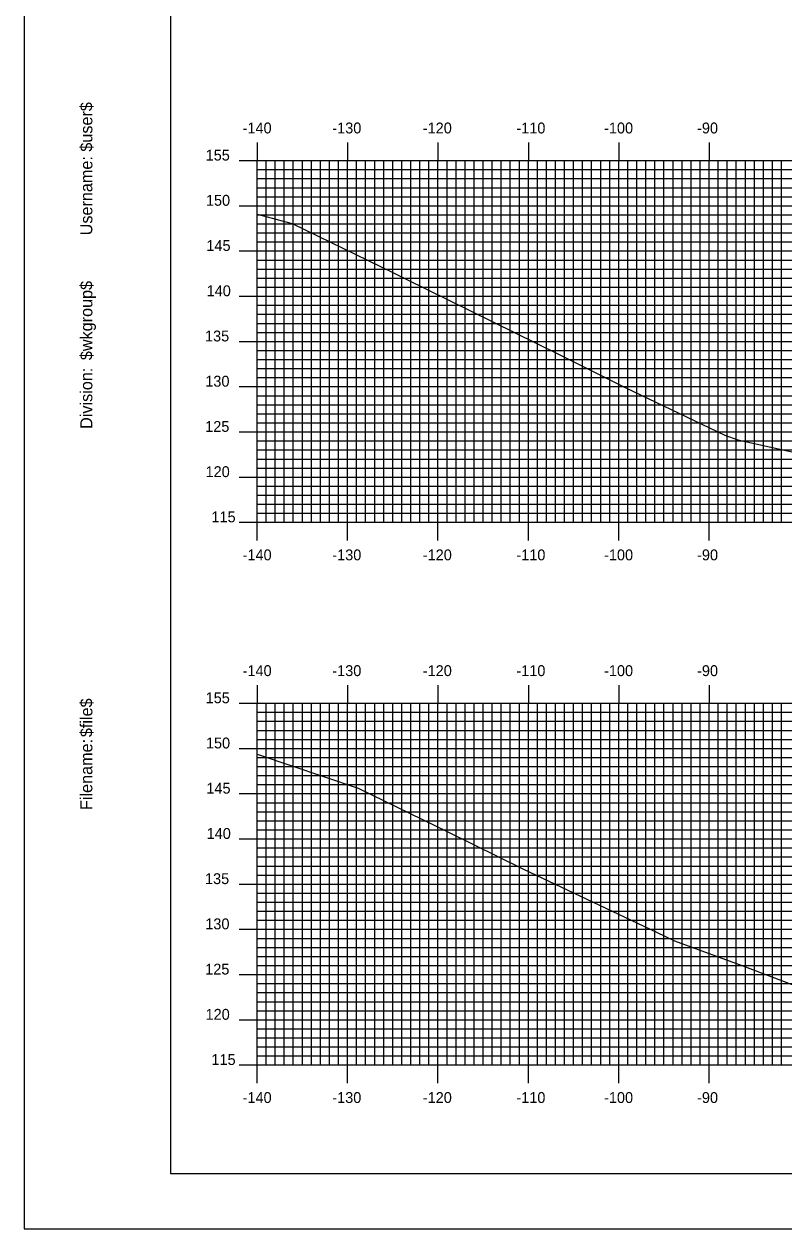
# Model space of a CAD drawing. Extents: x 851926 to 852269, y 366605 to 366825.
# Drawn here: x 851926.2 to 852010.2, y 366604.9 to 366738.1 of the extents above; entities that cross this region are included whole.
import ezdxf

# ---------------------------------------------------------------- set-up
doc = ezdxf.new("R2010")
doc.units = 0
for name, color, linetype in [('BORDER', 7, 'Continuous'), ('H_V ANNOTATION', 7, 'Continuous'), ('MAJOR', 7, 'Continuous'), ('MINOR', 7, 'Continuous'), ('PLOT BOUNDARY', 7, 'Continuous'), ('S_Roadway_Centerline', 7, 'Continuous')]:
    doc.layers.add(name, color=color, linetype=linetype)

msp = doc.modelspace()

# ---------------------------------------------------------------- linework, layer by layer
at = {"layer": 'BORDER'}
msp.add_lwpolyline([(851942.36, 366611.06), (852262.36, 366611.06), (852262.36, 366821.06), (851942.36, 366821.06)], close=True, dxfattribs=at)
at = {"layer": 'MAJOR'}
for p, q in [((851951.96, 366725.06), (851951.96, 366723.06)), ((851961.96, 366725.06), (851961.96, 366723.06)), ((851971.96, 366725.06), (851971.96, 366723.06)), ((851981.96, 366725.06), (851981.96, 366723.06)), ((851991.96, 366725.06), (851991.96, 366723.06)), ((852001.96, 366725.06), (852001.96, 366723.06)), ((851949.96, 366723.06), (851951.96, 366723.06)), ((851951.96, 366723.06), (852231.96, 366723.06)), ((851951.96, 366683.06), (851951.96, 366723.06)), ((851951.96, 366683.06), (851951.96, 366723.06)), ((851951.96, 366723.06), (852231.96, 366723.06)), ((851961.96, 366683.06), (851961.96, 366723.06)), ((851971.96, 366683.06), (851971.96, 366723.06)), ((851981.96, 366683.06), (851981.96, 366723.06)), ((851991.96, 366683.06), (851991.96, 366723.06)), ((852001.96, 366683.06), (852001.96, 366723.06)), ((851949.96, 366718.06), (851951.96, 366718.06)), ((851951.96, 366718.06), (852231.96, 366718.06)), ((851949.96, 366713.06), (851951.96, 366713.06)), ((851951.96, 366713.06), (852231.96, 366713.06)), ((851949.96, 366708.06), (851951.96, 366708.06)), ((851951.96, 366708.06), (852231.96, 366708.06)), ((851949.96, 366703.06), (851951.96, 366703.06)), ((851951.96, 366703.06), (852231.96, 366703.06)), ((851949.96, 366698.06), (851951.96, 366698.06)), ((851951.96, 366698.06), (852231.96, 366698.06)), ((851949.96, 366693.06), (851951.96, 366693.06)), ((851951.96, 366693.06), (852231.96, 366693.06)), ((851949.96, 366688.06), (851951.96, 366688.06)), ((851951.96, 366688.06), (852231.96, 366688.06)), ((851949.96, 366683.06), (851951.96, 366683.06)), ((851951.96, 366683.06), (852231.96, 366683.06)), ((851951.96, 366683.06), (852231.96, 366683.06)), ((851951.96, 366681.05), (851951.96, 366683.06)), ((851961.96, 366681.05), (851961.96, 366683.06)), ((851971.96, 366681.05), (851971.96, 366683.06)), ((851981.96, 366681.05), (851981.96, 366683.06)), ((851991.96, 366681.05), (851991.96, 366683.06)), ((852001.96, 366681.05), (852001.96, 366683.06)), ((851951.96, 366665.06), (851951.96, 366663.06)), ((851961.96, 366665.06), (851961.96, 366663.06)), ((851971.96, 366665.06), (851971.96, 366663.06)), ((851981.96, 366665.06), (851981.96, 366663.06)), ((851991.96, 366665.06), (851991.96, 366663.06)), ((852001.96, 366665.06), (852001.96, 366663.06)), ((851949.96, 366663.06), (851951.96, 366663.06)), ((851951.96, 366663.06), (852231.96, 366663.06)), ((851951.96, 366623.06), (851951.96, 366663.06)), ((851951.96, 366623.06), (851951.96, 366663.06)), ((851951.96, 366663.06), (852231.96, 366663.06)), ((851961.96, 366623.06), (851961.96, 366663.06)), ((851971.96, 366623.06), (851971.96, 366663.06)), ((851981.96, 366623.06), (851981.96, 366663.06)), ((851991.96, 366623.06), (851991.96, 366663.06)), ((852001.96, 366623.06), (852001.96, 366663.06)), ((851949.96, 366658.06), (851951.96, 366658.06)), ((851951.96, 366658.06), (852231.96, 366658.06)), ((851949.96, 366653.06), (851951.96, 366653.06)), ((851951.96, 366653.06), (852231.96, 366653.06)), ((851949.96, 366648.06), (851951.96, 366648.06)), ((851951.96, 366648.06), (852231.96, 366648.06)), ((851949.96, 366643.06), (851951.96, 366643.06)), ((851951.96, 366643.06), (852231.96, 366643.06)), ((851949.96, 366638.06), (851951.96, 366638.06)), ((851951.96, 366638.06), (852231.96, 366638.06)), ((851949.96, 366633.06), (851951.96, 366633.06)), ((851951.96, 366633.06), (852231.96, 366633.06)), ((851949.96, 366628.06), (851951.96, 366628.06)), ((851951.96, 366628.06), (852231.96, 366628.06)), ((851949.96, 366623.06), (851951.96, 366623.06)), ((851951.96, 366623.06), (852231.96, 366623.06)), ((851951.96, 366623.06), (852231.96, 366623.06)), ((851951.96, 366621.05), (851951.96, 366623.06)), ((851961.96, 366621.05), (851961.96, 366623.06)), ((851971.96, 366621.05), (851971.96, 366623.06)), ((851981.96, 366621.05), (851981.96, 366623.06)), ((851991.96, 366621.05), (851991.96, 366623.06)), ((852001.96, 366621.05), (852001.96, 366623.06))]:
    msp.add_line(p, q, dxfattribs=at)
at = {"layer": 'MINOR'}
for p, q in [((851951.96, 366722.06), (852231.96, 366722.06)), ((851951.96, 366722.06), (851953.97, 366722.06)), ((851952.96, 366683.06), (851952.96, 366723.06)), ((851953.96, 366683.06), (851953.96, 366723.06)), ((851954.96, 366683.06), (851954.96, 366723.06)), ((851955.96, 366683.06), (851955.96, 366723.06)), ((851956.96, 366683.06), (851956.96, 366723.06)), ((851957.96, 366683.06), (851957.96, 366723.06)), ((851958.96, 366683.06), (851958.96, 366723.06)), ((851959.96, 366683.06), (851959.96, 366723.06)), ((851960.96, 366683.06), (851960.96, 366723.06)), ((851962.96, 366683.06), (851962.96, 366723.06)), ((851963.96, 366683.06), (851963.96, 366723.06)), ((851964.96, 366683.06), (851964.96, 366723.06)), ((851965.96, 366683.06), (851965.96, 366723.06)), ((851966.96, 366683.06), (851966.96, 366723.06)), ((851967.96, 366683.06), (851967.96, 366723.06)), ((851968.96, 366683.06), (851968.96, 366723.06)), ((851969.96, 366683.06), (851969.96, 366723.06)), ((851970.96, 366683.06), (851970.96, 366723.06)), ((851972.96, 366683.06), (851972.96, 366723.06)), ((851973.96, 366683.06), (851973.96, 366723.06)), ((851974.96, 366683.06), (851974.96, 366723.06)), ((851975.96, 366683.06), (851975.96, 366723.06)), ((851976.96, 366683.06), (851976.96, 366723.06)), ((851977.96, 366683.06), (851977.96, 366723.06)), ((851978.96, 366683.06), (851978.96, 366723.06)), ((851979.96, 366683.06), (851979.96, 366723.06)), ((851980.96, 366683.06), (851980.96, 366723.06)), ((851982.96, 366683.06), (851982.96, 366723.06)), ((851983.96, 366683.06), (851983.96, 366723.06)), ((851984.96, 366683.06), (851984.96, 366723.06)), ((851985.96, 366683.06), (851985.96, 366723.06)), ((851986.96, 366683.06), (851986.96, 366723.06)), ((851987.96, 366683.06), (851987.96, 366723.06)), ((851988.96, 366683.06), (851988.96, 366723.06)), ((851989.96, 366683.06), (851989.96, 366723.06)), ((851990.96, 366683.06), (851990.96, 366723.06)), ((851992.96, 366683.06), (851992.96, 366723.06)), ((851993.96, 366683.06), (851993.96, 366723.06)), ((851994.96, 366683.06), (851994.96, 366723.06)), ((851995.96, 366683.06), (851995.96, 366723.06)), ((851996.96, 366683.06), (851996.96, 366723.06)), ((851997.96, 366683.06), (851997.96, 366723.06)), ((851998.96, 366683.06), (851998.96, 366723.06)), ((851999.96, 366683.06), (851999.96, 366723.06)), ((852000.96, 366683.06), (852000.96, 366723.06)), ((852002.96, 366683.06), (852002.96, 366723.06)), ((852003.96, 366683.06), (852003.96, 366723.06)), ((852004.96, 366683.06), (852004.96, 366723.06)), ((852005.96, 366683.06), (852005.96, 366723.06)), ((852006.96, 366683.06), (852006.96, 366723.06)), ((852007.96, 366683.06), (852007.96, 366723.06)), ((852008.96, 366683.06), (852008.96, 366723.06)), ((852009.96, 366683.06), (852009.96, 366723.06)), ((851951.96, 366721.06), (852231.96, 366721.06)), ((851951.96, 366721.06), (851953.97, 366721.06)), ((851951.96, 366720.06), (852231.96, 366720.06)), ((851951.96, 366720.06), (851953.97, 366720.06)), ((851951.96, 366719.06), (852231.96, 366719.06)), ((851951.96, 366719.06), (851953.97, 366719.06)), ((851951.96, 366717.06), (852231.96, 366717.06)), ((851951.96, 366717.06), (851953.97, 366717.06)), ((851951.96, 366716.06), (852231.96, 366716.06)), ((851951.96, 366716.06), (851953.97, 366716.06)), ((851951.96, 366715.06), (852231.96, 366715.06)), ((851951.96, 366715.06), (851953.97, 366715.06)), ((851951.96, 366714.06), (852231.96, 366714.06)), ((851951.96, 366714.06), (851953.97, 366714.06)), ((851951.96, 366712.06), (852231.96, 366712.06)), ((851951.96, 366712.06), (851953.97, 366712.06)), ((851951.96, 366711.06), (852231.96, 366711.06)), ((851951.96, 366711.06), (851953.97, 366711.06)), ((851951.96, 366710.06), (852231.96, 366710.06)), ((851951.96, 366710.06), (851953.97, 366710.06)), ((851951.96, 366709.06), (852231.96, 366709.06)), ((851951.96, 366709.06), (851953.97, 366709.06)), ((851951.96, 366707.06), (852231.96, 366707.06)), ((851951.96, 366707.06), (851953.97, 366707.06)), ((851951.96, 366706.06), (852231.96, 366706.06)), ((851951.96, 366706.06), (851953.97, 366706.06)), ((851951.96, 366705.06), (852231.96, 366705.06)), ((851951.96, 366705.06), (851953.97, 366705.06)), ((851951.96, 366704.06), (852231.96, 366704.06)), ((851951.96, 366704.06), (851953.97, 366704.06)), ((851951.96, 366702.06), (852231.96, 366702.06)), ((851951.96, 366702.06), (851953.97, 366702.06)), ((851951.96, 366701.06), (852231.96, 366701.06)), ((851951.96, 366701.06), (851953.97, 366701.06)), ((851951.96, 366700.06), (852231.96, 366700.06)), ((851951.96, 366700.06), (851953.97, 366700.06)), ((851951.96, 366699.06), (852231.96, 366699.06)), ((851951.96, 366699.06), (851953.97, 366699.06)), ((851951.96, 366697.06), (852231.96, 366697.06)), ((851951.96, 366697.06), (851953.97, 366697.06)), ((851951.96, 366696.06), (852231.96, 366696.06)), ((851951.96, 366696.06), (851953.97, 366696.06)), ((851951.96, 366695.06), (852231.96, 366695.06)), ((851951.96, 366695.06), (851953.97, 366695.06)), ((851951.96, 366694.06), (852231.96, 366694.06)), ((851951.96, 366694.06), (851953.97, 366694.06)), ((851951.96, 366692.06), (852231.96, 366692.06)), ((851951.96, 366692.06), (851953.97, 366692.06)), ((851951.96, 366691.06), (852231.96, 366691.06)), ((851951.96, 366691.06), (851953.97, 366691.06)), ((851951.96, 366690.06), (852231.96, 366690.06)), ((851951.96, 366690.06), (851953.97, 366690.06)), ((851951.96, 366689.06), (852231.96, 366689.06)), ((851951.96, 366689.06), (851953.97, 366689.06)), ((851951.96, 366687.06), (852231.96, 366687.06)), ((851951.96, 366687.06), (851953.97, 366687.06)), ((851951.96, 366686.06), (852231.96, 366686.06)), ((851951.96, 366686.06), (851953.97, 366686.06)), ((851951.96, 366685.06), (852231.96, 366685.06)), ((851951.96, 366685.06), (851953.97, 366685.06)), ((851951.96, 366684.06), (852231.96, 366684.06)), ((851951.96, 366684.06), (851953.97, 366684.06)), ((851951.96, 366662.06), (852231.96, 366662.06)), ((851951.96, 366662.06), (851953.97, 366662.06)), ((851952.96, 366623.06), (851952.96, 366663.06)), ((851953.96, 366623.06), (851953.96, 366663.06)), ((851954.96, 366623.06), (851954.96, 366663.06)), ((851955.96, 366623.06), (851955.96, 366663.06)), ((851956.96, 366623.06), (851956.96, 366663.06)), ((851957.96, 366623.06), (851957.96, 366663.06)), ((851958.96, 366623.06), (851958.96, 366663.06)), ((851959.96, 366623.06), (851959.96, 366663.06)), ((851960.96, 366623.06), (851960.96, 366663.06)), ((851962.96, 366623.06), (851962.96, 366663.06)), ((851963.96, 366623.06), (851963.96, 366663.06)), ((851964.96, 366623.06), (851964.96, 366663.06)), ((851965.96, 366623.06), (851965.96, 366663.06)), ((851966.96, 366623.06), (851966.96, 366663.06)), ((851967.96, 366623.06), (851967.96, 366663.06)), ((851968.96, 366623.06), (851968.96, 366663.06)), ((851969.96, 366623.06), (851969.96, 366663.06)), ((851970.96, 366623.06), (851970.96, 366663.06)), ((851972.96, 366623.06), (851972.96, 366663.06)), ((851973.96, 366623.06), (851973.96, 366663.06)), ((851974.96, 366623.06), (851974.96, 366663.06)), ((851975.96, 366623.06), (851975.96, 366663.06)), ((851976.96, 366623.06), (851976.96, 366663.06)), ((851977.96, 366623.06), (851977.96, 366663.06)), ((851978.96, 366623.06), (851978.96, 366663.06)), ((851979.96, 366623.06), (851979.96, 366663.06)), ((851980.96, 366623.06), (851980.96, 366663.06)), ((851982.96, 366623.06), (851982.96, 366663.06)), ((851983.96, 366623.06), (851983.96, 366663.06)), ((851984.96, 366623.06), (851984.96, 366663.06)), ((851985.96, 366623.06), (851985.96, 366663.06)), ((851986.96, 366623.06), (851986.96, 366663.06)), ((851987.96, 366623.06), (851987.96, 366663.06)), ((851988.96, 366623.06), (851988.96, 366663.06)), ((851989.96, 366623.06), (851989.96, 366663.06)), ((851990.96, 366623.06), (851990.96, 366663.06)), ((851992.96, 366623.06), (851992.96, 366663.06)), ((851993.96, 366623.06), (851993.96, 366663.06)), ((851994.96, 366623.06), (851994.96, 366663.06)), ((851995.96, 366623.06), (851995.96, 366663.06)), ((851996.96, 366623.06), (851996.96, 366663.06)), ((851997.96, 366623.06), (851997.96, 366663.06)), ((851998.96, 366623.06), (851998.96, 366663.06)), ((851999.96, 366623.06), (851999.96, 366663.06)), ((852000.96, 366623.06), (852000.96, 366663.06)), ((852002.96, 366623.06), (852002.96, 366663.06)), ((852003.96, 366623.06), (852003.96, 366663.06)), ((852004.96, 366623.06), (852004.96, 366663.06)), ((852005.96, 366623.06), (852005.96, 366663.06)), ((852006.96, 366623.06), (852006.96, 366663.06)), ((852007.96, 366623.06), (852007.96, 366663.06)), ((852008.96, 366623.06), (852008.96, 366663.06)), ((852009.96, 366623.06), (852009.96, 366663.06)), ((851951.96, 366661.06), (852231.96, 366661.06)), ((851951.96, 366661.06), (851953.97, 366661.06)), ((851951.96, 366660.06), (852231.96, 366660.06)), ((851951.96, 366660.06), (851953.97, 366660.06)), ((851951.96, 366659.06), (852231.96, 366659.06)), ((851951.96, 366659.06), (851953.97, 366659.06)), ((851951.96, 366657.06), (852231.96, 366657.06)), ((851951.96, 366657.06), (851953.97, 366657.06)), ((851951.96, 366656.06), (852231.96, 366656.06)), ((851951.96, 366656.06), (851953.97, 366656.06)), ((851951.96, 366655.06), (852231.96, 366655.06)), ((851951.96, 366655.06), (851953.97, 366655.06)), ((851951.96, 366654.06), (852231.96, 366654.06)), ((851951.96, 366654.06), (851953.97, 366654.06)), ((851951.96, 366652.06), (852231.96, 366652.06)), ((851951.96, 366652.06), (851953.97, 366652.06)), ((851951.96, 366651.06), (852231.96, 366651.06)), ((851951.96, 366651.06), (851953.97, 366651.06)), ((851951.96, 366650.06), (852231.96, 366650.06)), ((851951.96, 366650.06), (851953.97, 366650.06)), ((851951.96, 366649.06), (852231.96, 366649.06)), ((851951.96, 366649.06), (851953.97, 366649.06)), ((851951.96, 366647.06), (852231.96, 366647.06)), ((851951.96, 366647.06), (851953.97, 366647.06)), ((851951.96, 366646.06), (852231.96, 366646.06)), ((851951.96, 366646.06), (851953.97, 366646.06)), ((851951.96, 366645.06), (852231.96, 366645.06)), ((851951.96, 366645.06), (851953.97, 366645.06)), ((851951.96, 366644.06), (852231.96, 366644.06)), ((851951.96, 366644.06), (851953.97, 366644.06)), ((851951.96, 366642.06), (852231.96, 366642.06)), ((851951.96, 366642.06), (851953.97, 366642.06)), ((851951.96, 366641.06), (852231.96, 366641.06)), ((851951.96, 366641.06), (851953.97, 366641.06)), ((851951.96, 366640.06), (852231.96, 366640.06)), ((851951.96, 366640.06), (851953.97, 366640.06)), ((851951.96, 366639.06), (852231.96, 366639.06)), ((851951.96, 366639.06), (851953.97, 366639.06)), ((851951.96, 366637.06), (852231.96, 366637.06)), ((851951.96, 366637.06), (851953.97, 366637.06)), ((851951.96, 366636.06), (852231.96, 366636.06)), ((851951.96, 366636.06), (851953.97, 366636.06)), ((851951.96, 366635.06), (852231.96, 366635.06)), ((851951.96, 366635.06), (851953.97, 366635.06)), ((851951.96, 366634.06), (852231.96, 366634.06)), ((851951.96, 366634.06), (851953.97, 366634.06)), ((851951.96, 366632.06), (852231.96, 366632.06)), ((851951.96, 366632.06), (851953.97, 366632.06)), ((851951.96, 366631.06), (852231.96, 366631.06)), ((851951.96, 366631.06), (851953.97, 366631.06)), ((851951.96, 366630.06), (852231.96, 366630.06)), ((851951.96, 366630.06), (851953.97, 366630.06)), ((851951.96, 366629.06), (852231.96, 366629.06)), ((851951.96, 366629.06), (851953.97, 366629.06)), ((851951.96, 366627.06), (852231.96, 366627.06)), ((851951.96, 366627.06), (851953.97, 366627.06)), ((851951.96, 366626.06), (852231.96, 366626.06)), ((851951.96, 366626.06), (851953.97, 366626.06)), ((851951.96, 366625.06), (852231.96, 366625.06)), ((851951.96, 366625.06), (851953.97, 366625.06)), ((851951.96, 366624.06), (852231.96, 366624.06)), ((851951.96, 366624.06), (851953.97, 366624.06))]:
    msp.add_line(p, q, dxfattribs=at)
at = {"layer": 'PLOT BOUNDARY'}
msp.add_lwpolyline([(851926.18, 366604.94), (852266.18, 366604.94), (852266.18, 366824.94), (851926.18, 366824.94)], close=True, dxfattribs=at)
at = {"layer": 'S_Roadway_Centerline'}
for points in [[(851951.96, 366717.13), (851955.82, 366716.11), (851967.04, 366710.66), (851968.35, 366709.98), (851985.28, 366701.65), (851992.68, 366697.97), (852003.7, 366692.7), (852005.12, 366692.17), (852014.6, 366690.08)], [(851951.96, 366657.41), (851963.14, 366653.68), (851973.05, 366648.83), (851981.42, 366644.72), (851996.14, 366637.73), (851998.11, 366636.8), (852005.69, 366634.03), (852015.32, 366630.36)]]:
    msp.add_lwpolyline(points, dxfattribs=at)

# ---------------------------------------------------------------- texts
at = {"layer": 'BORDER'}
for s, p in [('$user$', (851933.73, 366724.04)), ('Username:', (851933.73, 366714.79)), ('$wkgroup$', (851933.73, 366700.99)), ('Division:', (851933.73, 366693.39)), ('$file$', (851933.73, 366659.31)), ('Filename:', (851933.73, 366651.25))]:
    msp.add_text(s, height=1.339, rotation=90, dxfattribs=at).set_placement(p)
at = {"layer": 'H_V ANNOTATION'}
for s, p in [('-140', (851950.35, 366726.06)), ('-130', (851960.27, 366726.06)), ('-120', (851970.28, 366726.06)), ('-110', (851980.63, 366726.06)), ('-100', (851990.33, 366726.06)), ('-90', (852000.62, 366726.06)), ('155', (851946.26, 366723.06)), ('150', (851946.29, 366718.06)), ('145', (851946.34, 366713.06)), ('140', (851946.37, 366708.06)), ('135', (851946.19, 366703.06)), ('130', (851946.22, 366698.06)), ('125', (851946.21, 366693.06)), ('120', (851946.25, 366688.06)), ('115', (851946.9, 366683.06)), ('-140', (851950.35, 366678.86)), ('-130', (851960.27, 366678.86)), ('-120', (851970.28, 366678.86)), ('-110', (851980.63, 366678.86)), ('-100', (851990.33, 366678.86)), ('-90', (852000.62, 366678.86)), ('-140', (851950.35, 366666.06)), ('-130', (851960.27, 366666.06)), ('-120', (851970.28, 366666.06)), ('-110', (851980.63, 366666.06)), ('-100', (851990.33, 366666.06)), ('-90', (852000.62, 366666.06)), ('155', (851946.26, 366663.06)), ('150', (851946.29, 366658.06)), ('145', (851946.34, 366653.06)), ('140', (851946.37, 366648.06)), ('135', (851946.19, 366643.06)), ('130', (851946.22, 366638.06)), ('125', (851946.21, 366633.06)), ('120', (851946.25, 366628.06)), ('115', (851946.9, 366623.06)), ('-140', (851950.35, 366618.86)), ('-130', (851960.27, 366618.86)), ('-120', (851970.28, 366618.86)), ('-110', (851980.63, 366618.86)), ('-100', (851990.33, 366618.86)), ('-90', (852000.62, 366618.86))]:
    msp.add_text(s, height=1.2, dxfattribs=at).set_placement(p)
at = {"layer": 'MAJOR'}
for p in [(851951.96, 366683.06), (851951.96, 366623.06)]:
    msp.add_text('-', height=0.012, dxfattribs=at).set_placement(p)

doc.saveas('drawing.dxf')
